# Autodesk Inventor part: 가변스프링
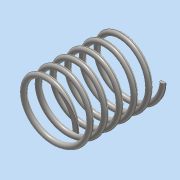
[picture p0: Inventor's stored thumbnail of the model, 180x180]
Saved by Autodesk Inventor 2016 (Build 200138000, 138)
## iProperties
Created: 2018-11
Part Number: 가변스프링
Material: 스테인레스 스틸
Document SubType Name: Modeling
Designer: 공506_43
Density: 8 g/cm^3
Appearance: 반연마
Mass: 84.1963 g
Surface Area: 106.449 cm^2
Volume: 10.5245 cm^3
Author: 공506_43
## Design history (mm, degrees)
sketch "스케치1"
  geometry: L1 (0, 0)-(22.5, 0); L2 (22.5, 0)-(22.5, 67.25); L3 (22.5, 67.25)-(0, 67.25); L4 (0, 67.25)-(0, 0); C1 r 2 at (22.5, 0)
  constraints: 8 end point, 2 parallel, 1 centre point, 1 coincident, 1 horizontal, 1 perpendicular
  dimensions: "d0" = 22.5 distance of L2.end L3.end; "d1" = 67.25 distance of L3.end L1.start (derived); "d2" = 4 diameter of C1
feature "코일1" sketch "스케치1" pitch "d3" = 10; turns "d5" = 6; dims "d4" = 67.25 (= d1), "d6" = 0, angle "d7" = 90 deg, angle "d8" = 90 deg, "d9" = 0, "d10" = 0
sketch "스케치2"
  geometry: L1 (0, 70.18)-(67.25, 70.18); L2 (67.25, 70.18)-(67.25, -70.18); L3 (67.25, -70.18)-(0, -70.18); L4 (0, -70.18)-(0, 70.18); 3 further points
  constraints: 8 end point, 2 midpoint, 2 parallel, 1 coincident, 1 horizontal, 1 horizontal alignment, 1 perpendicular
  dimensions: "d11" = 140.35977 distance of L1.end L2.end; "d12" = 67.25 distance of L1.start L1.end (= d1)
extrude "돌출1" sketch "스케치2" stored distance "d13" = 600; taper "d14" = 0 deg
node "솔리드1"
